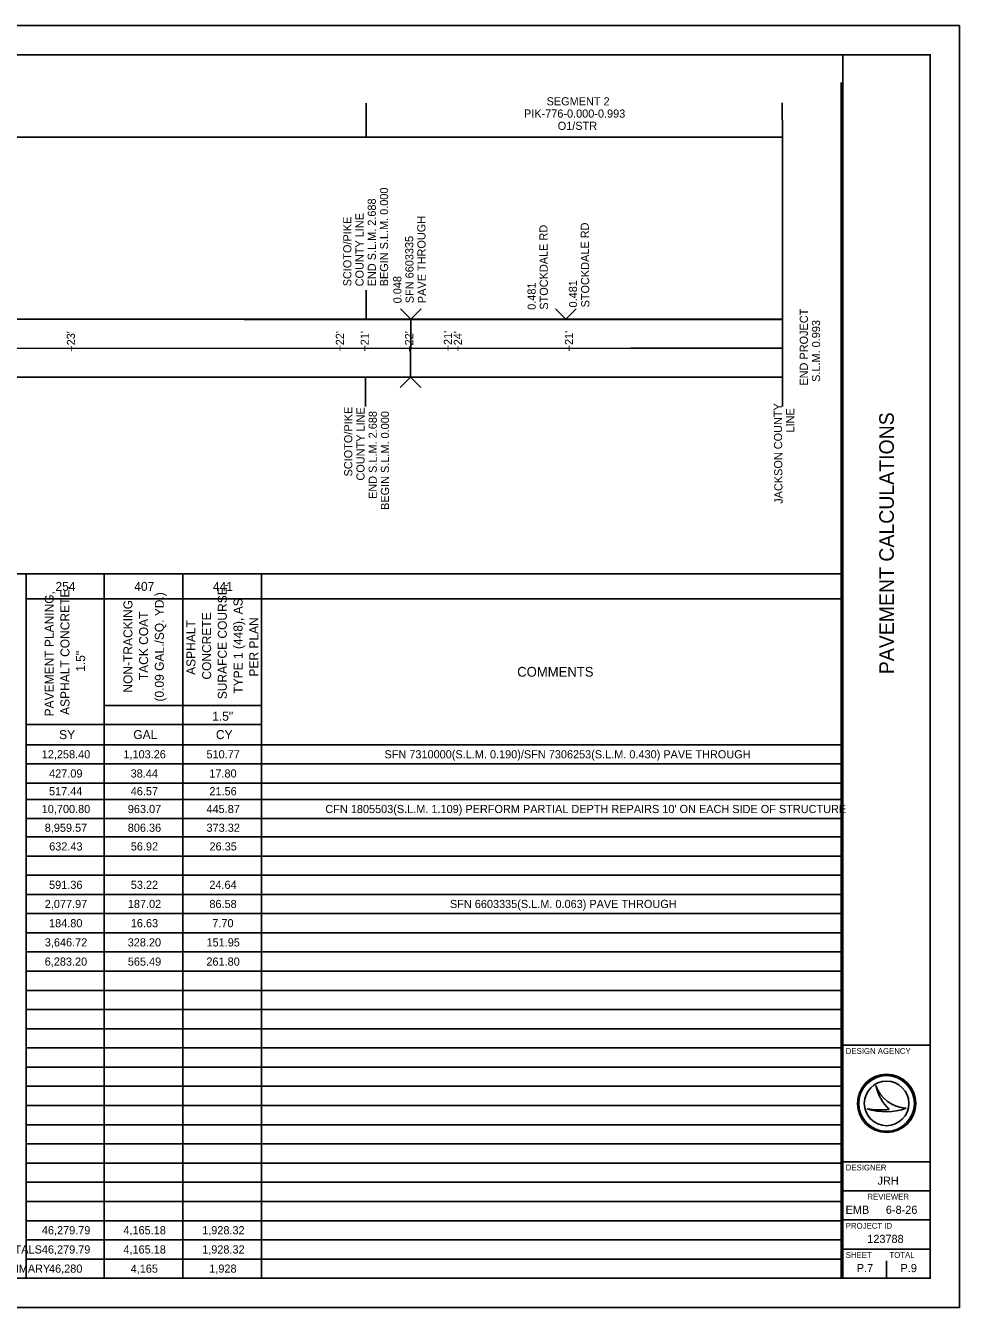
# Model space of a CAD drawing. Extents: x 1.5 to 35.5, y 0.5 to 22.5.
# Drawn here: x 19.47 to 35.5, y 0.5 to 22.5 of the extents above; entities that cross this region are included whole.
import ezdxf

# ---------------------------------------------------------------- set-up
doc = ezdxf.new("R2010")
doc.units = 0
for name, color, linetype in [('Default', 7, 'Continuous'), ('SH_Border', 7, 'Continuous'), ('SH_Cut_Line', 7, 'Continuous'), ('SH_Data', 7, 'Continuous'), ('SH_Text', 7, 'Continuous')]:
    doc.layers.add(name, color=color, linetype=linetype)

msp = doc.modelspace()

# ---------------------------------------------------------------- linework, layer by layer
at = {"layer": 'Default'}
for p, q in [((33.471, 21.522), (33.471, 1)), ((25.315, 20.584), (25.314, 21.172)), ((32.461, 20.585), (32.46, 21.173)), ((4.037, 20.585), (32.461, 20.585)), ((32.461, 19.462), (32.461, 20.585)), ((32.461, 20.585), (32.461, 17.462)), ((25.315, 17.962), (25.315, 17.462)), ((25.906, 17.64), (26.082, 17.463)), ((26.082, 17.463), (26.259, 17.64)), ((28.568, 17.639), (28.745, 17.462)), ((28.745, 17.462), (28.922, 17.639)), ((4.037, 17.462), (32.461, 17.462)), ((26.082, 17.463), (26.078, 16.464)), ((32.461, 17.462), (32.461, 16.464)), ((32.461, 17.462), (32.461, 16.963)), ((29.854, 16.963), (13.959, 16.959)), ((29.854, 16.963), (30.315, 16.963)), ((30.315, 16.963), (32.461, 16.963)), ((32.461, 16.956), (32.461, 16.464)), ((32.461, 16.464), (4.037, 16.464)), ((25.303, 16.464), (25.304, 15.964)), ((25.901, 16.288), (26.078, 16.464)), ((26.078, 16.464), (26.254, 16.288)), ((26.99, 16.472), (26.99, 16.466)), ((27.826, 16.468), (27.826, 16.466)), ((32.461, 16.464), (32.462, 15.964)), ((17.22, 13.089), (19.482, 13.089)), ((19.46, 13.089), (33.471, 13.089)), ((19.482, 13.089), (19.482, 1)), ((20.821, 13.089), (20.821, 1)), ((22.172, 13.089), (22.172, 1)), ((23.522, 13.089), (23.522, 1)), ((19.482, 12.661), (33.471, 12.661)), ((20.821, 10.833), (23.522, 10.833)), ((19.482, 10.504), (23.522, 10.504)), ((19.482, 10.158), (33.471, 10.158)), ((19.482, 9.828), (33.471, 9.828)), ((19.482, 9.499), (33.471, 9.499)), ((19.482, 9.219), (33.471, 9.219)), ((19.482, 8.889), (33.471, 8.889)), ((19.482, 8.576), (33.471, 8.576)), ((19.482, 8.247), (33.471, 8.247)), ((19.482, 7.918), (33.471, 7.918)), ((19.482, 7.588), (33.471, 7.588)), ((19.482, 7.259), (33.471, 7.259)), ((19.482, 6.929), (33.471, 6.929)), ((19.482, 6.6), (33.471, 6.6)), ((19.482, 6.271), (33.471, 6.271)), ((19.482, 5.941), (33.471, 5.941)), ((19.482, 5.612), (33.471, 5.612)), ((19.482, 5.282), (33.471, 5.282)), ((19.482, 4.953), (33.471, 4.953)), ((19.482, 4.624), (33.471, 4.624)), ((19.482, 4.294), (33.471, 4.294)), ((19.482, 3.965), (33.471, 3.965)), ((19.482, 3.635), (33.471, 3.635)), ((19.482, 3.306), (33.471, 3.306)), ((19.482, 2.976), (33.471, 2.976)), ((19.482, 2.647), (33.471, 2.647)), ((19.482, 2.318), (33.471, 2.318)), ((19.482, 1.988), (33.471, 1.988)), ((19.482, 1.659), (33.471, 1.659)), ((19.482, 1.329), (33.471, 1.329)), ((3, 1), (19.482, 1)), ((19.46, 1), (33.471, 1))]:
    msp.add_line(p, q, dxfattribs=at)
msp.add_lwpolyline([(13.959, 17.462), (32.462, 17.449), (32.461, 16.464), (26.078, 16.464), (26.078, 16.464), (26.077, 16.464), (13.959, 16.463)], close=True, dxfattribs=at)
at = {"layer": 'SH_Border'}
for p, q in [((33.5, 1), (33.5, 22)), ((33.5, 5), (35, 5)), ((33.5, 3), (35, 3)), ((33.5, 2.5), (35, 2.5)), ((33.5, 2), (35, 2)), ((33.5, 1.5), (35, 1.5))]:
    msp.add_line(p, q, dxfattribs=at)
msp.add_lwpolyline([(3, 22), (35, 22), (35, 1), (3, 1)], close=True, dxfattribs=at)
at = {"layer": 'SH_Cut_Line'}
msp.add_lwpolyline([(1.5, 0.5), (35.5, 0.5), (35.5, 22.5), (1.5, 22.5)], close=True, dxfattribs=at)
at = {"layer": 'SH_Data'}
for p, q in [((34.067, 4.31), (34.067, 4.31)), ((34.25, 4), (34.25, 4)), ((33.917, 3.91), (33.917, 3.91)), ((34.587, 3.919), (34.587, 3.919)), ((33.875, 1.175), (33.875, 1.175)), ((34.25, 1), (34.25, 1.3))]:
    msp.add_line(p, q, dxfattribs=at)
for radius in [0.5, 0.477, 0.477, 0.382]:
    msp.add_circle((34.25, 4), radius, dxfattribs=at)
for centre, radius, start, end in [((34.616, 4.498), 0.58, 198.9257, 198.9319), ((34.847, 4.47), 0.796, 191.6379, 191.6421), ((34.616, 4.498), 0.58, 198.9319, 267.1657), ((34.847, 4.47), 0.796, 191.6421, 226.0947), ((34.239, 4.87), 1.013, 251.4576, 290.0832), ((34.148, 5.154), 1.266, 259.4964, 259.4995), ((34.239, 4.87), 1.013, 251.4527, 251.4576), ((34.148, 5.154), 1.266, 259.4995, 276.6672)]:
    msp.add_arc(centre, radius, start, end, dxfattribs=at)
at = {"layer": 'SH_Text'}
msp.add_line((4.037, 16.464), (32.461, 16.464), dxfattribs=at)

# ---------------------------------------------------------------- texts
at = {"layer": 'Default'}
for s, height, p in [('SEGMENT 2', 0.14, (28.414, 21.131)), ('PIK-776-0.000-0.993', 0.14, (28.026, 20.921)), ('O1/STR', 0.14, (28.605, 20.711)), ('254', 0.154, (19.983, 12.798)), ('407', 0.154, (21.336, 12.798)), ('441', 0.154, (22.687, 12.798)), ('COMMENTS', 0.168, (27.909, 11.325)), ('1.5"', 0.154, (22.673, 10.569)), ('SY', 0.154, (20.045, 10.254)), ('GAL', 0.154, (21.319, 10.254)), ('CY', 0.154, (22.737, 10.254)), ('12,258.40', 0.14, (19.747, 9.923)), ('1,103.26', 0.14, (21.149, 9.923)), ('510.77', 0.14, (22.575, 9.923)), ('SFN 7310000(S.L.M. 0.190)/SFN 7306253(S.L.M. 0.430) PAVE THROUGH', 0.14, (25.631, 9.923)), ('427.09', 0.14, (19.874, 9.594)), ('38.44', 0.14, (21.273, 9.594)), ('17.80', 0.14, (22.624, 9.594)), ('517.44', 0.14, (19.872, 9.289)), ('46.57', 0.14, (21.275, 9.289)), ('21.56', 0.14, (22.625, 9.289)), ('10,700.80', 0.14, (19.747, 8.984)), ('963.07', 0.14, (21.225, 8.984)), ('445.87', 0.14, (22.575, 8.984)), ("CFN 1805503(S.L.M. 1.109) PERFORM PARTIAL DEPTH REPAIRS 10' ON EACH SIDE OF STRUCTURE", 0.14, (24.616, 8.984)), ('8,959.57', 0.14, (19.799, 8.663)), ('806.36', 0.14, (21.224, 8.663)), ('373.32', 0.14, (22.576, 8.663)), ('632.43', 0.14, (19.875, 8.342)), ('56.92', 0.14, (21.276, 8.342)), ('26.35', 0.14, (22.627, 8.342)), ('591.36', 0.14, (19.873, 7.683)), ('53.22', 0.14, (21.276, 7.683)), ('24.64', 0.14, (22.624, 7.683)), ('2,077.97', 0.14, (19.799, 7.354)), ('187.02', 0.14, (21.225, 7.354)), ('86.58', 0.14, (22.625, 7.354)), ('SFN 6603335(S.L.M. 0.063) PAVE THROUGH', 0.14, (26.755, 7.354)), ('184.80', 0.14, (19.873, 7.024)), ('16.63', 0.14, (21.276, 7.024)), ('7.70', 0.14, (22.675, 7.024)), ('3,646.72', 0.14, (19.8, 6.695)), ('328.20', 0.14, (21.223, 6.695)), ('151.95', 0.14, (22.576, 6.695)), ('6,283.20', 0.14, (19.798, 6.365)), ('565.49', 0.14, (21.225, 6.365)), ('261.80', 0.14, (22.574, 6.365)), ('46,279.79', 0.14, (19.749, 1.754)), ('4,165.18', 0.14, (21.149, 1.754)), ('1,928.32', 0.14, (22.501, 1.754)), ('THIS SHEET TOTALS', 0.14, (17.867, 1.424)), ('46,279.79', 0.14, (19.749, 1.424)), ('4,165.18', 0.14, (21.149, 1.424)), ('1,928.32', 0.14, (22.501, 1.424)), ('TOTALS CARRIED TO GENERAL SUMMARY', 0.14, (16.003, 1.095)), ('46,280', 0.14, (19.872, 1.095)), ('4,165', 0.14, (21.274, 1.095)), ('1,928', 0.14, (22.623, 1.095))]:
    msp.add_text(s, height=height, dxfattribs=at).set_placement(p)
for s, height, rotation, p in [('BEGIN S.L.M. 0.000', 0.14, 90, (25.693, 18.025)), ('END S.L.M. 2.688', 0.14, 90, (25.483, 18.025)), ('SCIOTO/PIKE ', 0.14, 90, (25.063, 18.025)), ('COUNTY LINE', 0.14, 90, (25.273, 18.025)), ('PAVE THROUGH', 0.14, 90.4647, (26.344, 17.737)), ('STOCKDALE RD', 0.14, 90.3717, (28.438, 17.625)), ('STOCKDALE RD', 0.14, 90.3717, (29.148, 17.664)), ('SFN 6603335', 0.14, 90.4647, (26.134, 17.736)), ('0.048', 0.14, 90.4647, (25.924, 17.734)), ('0.481', 0.14, 90.3717, (28.228, 17.623)), ('0.481', 0.14, 90.3717, (28.938, 17.663)), ('END PROJECT', 0.14, 90, (32.899, 16.321)), ('S.L.M. 0.993', 0.14, 90, (33.109, 16.385)), ("+23'", 0.14, 91.6352, (20.324, 16.905)), ("+22'", 0.14, 90, (24.936, 16.905)), ("+22'", 0.14, 90, (26.124, 16.902)), ("+24'", 0.14, 90.225, (26.962, 16.904)), ('SCIOTO/PIKE ', 0.14, 90, (25.079, 14.762)), ('COUNTY LINE', 0.14, 90, (25.289, 14.691)), ('     END S.L.M. 2.688', 0.14, 90, (25.499, 14.116)), ('BEGIN S.L.M. 0.000', 0.14, 90, (25.709, 14.187)), ('JACKSON COUNTY ', 0.14, 90.3901, (32.465, 14.293)), ('LINE', 0.14, 90.3901, (32.667, 15.516)), ('PAVEMENT PLANING, ', 0.154, 90, (19.953, 10.643)), ('ASPHALT CONCRETE, ', 0.154, 90, (20.223, 10.669)), ('(0.09 GAL./SQ. YD.)', 0.154, 90, (21.843, 10.898)), ('SURAFCE COURSE, ', 0.154, 90, (22.924, 10.938)), ('NON-TRACKING ', 0.154, 90, (21.304, 11.052)), ('TYPE 1 (448), AS ', 0.154, 90, (23.194, 11.033)), ('TACK COAT', 0.154, 90, (21.573, 11.265)), ('CONCRETE ', 0.154, 90, (22.655, 11.275)), ('PER PLAN', 0.154, 90, (23.463, 11.327)), ('ASPHALT ', 0.154, 90, (22.385, 11.356)), ('1.5"', 0.154, 90, (20.492, 11.409))]:
    msp.add_text(s, height=height, rotation=rotation, dxfattribs=at).set_placement(p)
at = {"layer": 'SH_Data'}
msp.add_text('PAVEMENT CALCULATIONS', height=0.25, rotation=90, dxfattribs=at).set_placement((34.375, 11.368))
for s, height, p in [('DESIGN AGENCY', 0.1, (33.55, 4.85)), ('DESIGNER', 0.1, (33.55, 2.85)), ('JRH', 0.14, (34.095, 2.605)), ('REVIEWER', 0.1, (33.922, 2.35)), ('EMB', 0.14, (33.547, 2.105)), ('6-8-26', 0.14, (34.238, 2.105)), ('PROJECT ID', 0.1, (33.55, 1.85)), ('123788', 0.14, (33.919, 1.605)), ('SHEET', 0.1, (33.55, 1.35)), ('TOTAL', 0.1, (34.3, 1.35)), ('P.7', 0.14, (33.739, 1.105)), ('P.9', 0.14, (34.49, 1.105))]:
    msp.add_text(s, height=height, dxfattribs=at).set_placement(p)
at = {"layer": 'SH_Text'}
for p in [(25.362, 16.905), (26.79, 16.91), (28.868, 16.909)]:
    msp.add_text("+21'", height=0.14, rotation=90, dxfattribs=at).set_placement(p)

doc.saveas('drawing.dxf')
